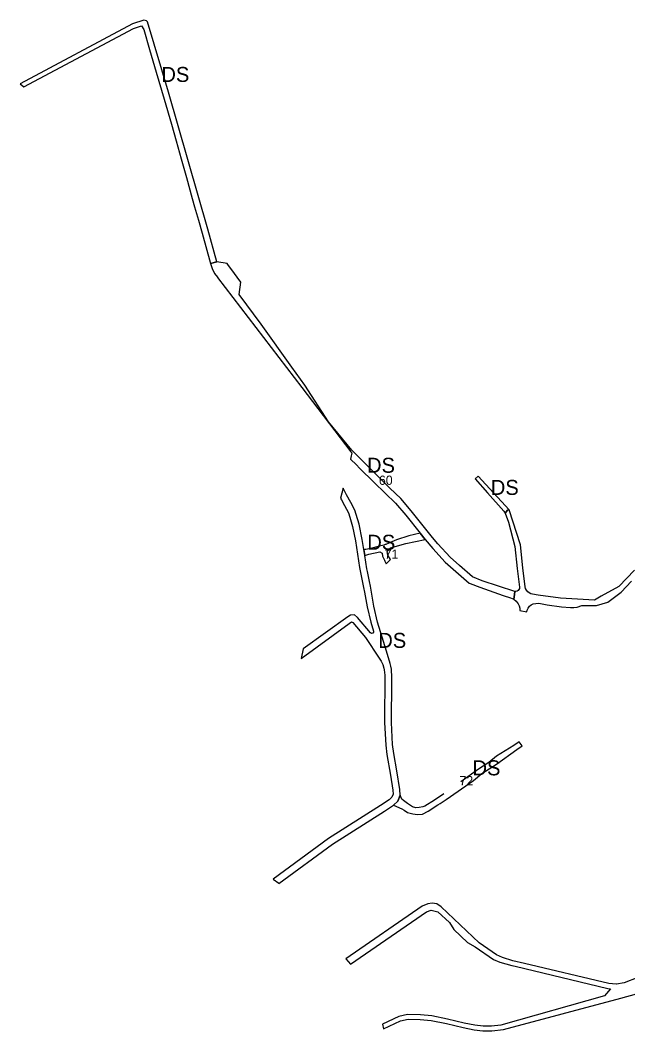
# Model space of a CAD drawing. Extents: x -535435 to -532834, y -1165802 to -1163866.
# Drawn here: x -535435 to -534910, y -1165594 to -1164720 of the extents above; entities that cross this region are included whole.
import ezdxf

# ---------------------------------------------------------------- set-up
doc = ezdxf.new("R2010")
doc.units = 0
for name, color, linetype in [('Level 4', 7, 'Continuous'), ('Level 43', 7, 'Continuous'), ('Level 5', 7, 'Continuous'), ('Level 61', 7, 'Continuous')]:
    doc.layers.add(name, color=color, linetype=linetype)

msp = doc.modelspace()

# ---------------------------------------------------------------- linework, layer by layer
at = {"layer": 'Level 4'}
for points in [[(-535330.07, -1164724.66), (-535328.05, -1164727.88), (-535322.98, -1164745.04), (-535317.16, -1164764.78), (-535310.26, -1164788.12), (-535304.15, -1164809.81), (-535300.1, -1164824.22), (-535295.73, -1164839.71), (-535291.17, -1164855.92), (-535286.04, -1164874.13), (-535284.01, -1164881.32), (-535280.81, -1164892.67), (-535277.63, -1164903.97), (-535270.21, -1164930.28), (-535264.94, -1164928.87), (-535272.55, -1164900.37), (-535306.74, -1164781.96), (-535324.72, -1164721.28), (-535325.54, -1164720.29), (-535327.93, -1164719.8), (-535337.8, -1164722.86), (-535434.81, -1164774.69), (-535431.57, -1164777.51), (-535336.95, -1164727.03)], [(-535015.48, -1165146.04), (-535013.47, -1165143.59), (-535012, -1165143.18), (-535038.78, -1165114.13), (-535041.39, -1165116.45), (-535030.79, -1165128.55), (-535016.81, -1165144.52)], [(-535148.99, -1165136.79), (-535152.58, -1165130.22), (-535155.67, -1165124.57), (-535157.81, -1165133.15), (-535157, -1165134.64), (-535154.36, -1165139.49), (-535151.12, -1165145.75), (-535149.97, -1165149.47), (-535147.45, -1165157.58), (-535144.99, -1165170.01), (-535141.61, -1165193.12), (-535139.69, -1165201.82), (-535137.97, -1165210.49), (-535137.13, -1165214.5), (-535134.97, -1165227.14), (-535131.59, -1165240.5), (-535129.33, -1165248.15), (-535129.39, -1165249.15), (-535130.06, -1165249.89), (-535131.05, -1165250.05), (-535131.92, -1165249.54), (-535143.16, -1165236.25), (-535145.86, -1165234.18), (-535149.38, -1165234.32), (-535151.45, -1165235.77), (-535190.12, -1165263.37), (-535192.03, -1165271.67), (-535150.48, -1165241.56), (-535148.51, -1165240.07), (-535147.29, -1165240.66), (-535136.4, -1165253.54), (-535124.44, -1165271.51), (-535122.72, -1165274.17), (-535121.35, -1165277.05), (-535120.36, -1165280.09), (-535120.06, -1165281.7), (-535119.6, -1165286.31), (-535119.85, -1165327.25), (-535118.83, -1165346.66), (-535117.83, -1165354.96), (-535114.74, -1165372.78), (-535112.59, -1165385.66), (-535112.44, -1165389.06), (-535113.51, -1165391.75), (-535115.81, -1165393.93), (-535123.19, -1165398.9), (-535168.13, -1165427.38), (-535216.21, -1165462.69), (-535211.33, -1165466.2), (-535211.12, -1165466.4), (-535164.75, -1165432.34), (-535119.96, -1165403.95), (-535112.03, -1165398.61), (-535108.43, -1165395.19), (-535106.38, -1165390.08), (-535106.61, -1165385.02), (-535109.32, -1165368.87), (-535111.89, -1165354.08), (-535112.85, -1165346.14), (-535113.85, -1165327.11), (-535113.63, -1165291.11), (-535113.6, -1165285.86), (-535113.67, -1165283.44), (-535113.92, -1165280.97), (-535114.34, -1165278.52), (-535114.92, -1165276.17), (-535118, -1165265.36), (-535125.87, -1165240.38), (-535128.96, -1165226.67), (-535132.1, -1165209.24), (-535132.91, -1165205.19), (-535134.64, -1165196.44), (-535135.08, -1165194.24), (-535136.92, -1165182.6), (-535137.7, -1165177.68), (-535139.07, -1165168.99), (-535141.76, -1165155.67), (-535144.39, -1165147.19), (-535145.54, -1165143.47)]]:
    msp.add_lwpolyline(points, close=True, dxfattribs=at)
msp.add_lwpolyline([(-534877.24, -1165538.36), (-534912.68, -1165552.42), (-534919.2, -1165553.5), (-534919.44, -1165553.53), (-534926.03, -1165552.84), (-534998.84, -1165535.55), (-535008.78, -1165533.19), (-535017.91, -1165530.5), (-535022.95, -1165527.99), (-535037.98, -1165517.6), (-535070.93, -1165486.65), (-535074.54, -1165483.89), (-535078.53, -1165483.39), (-535082.4, -1165484.03), (-535087.18, -1165485.86), (-535153.29, -1165531.56), (-535149.25, -1165536.15), (-535083.65, -1165491.01), (-535079.48, -1165489.46), (-535073.7, -1165490.85), (-535063.55, -1165500.03), (-535059.98, -1165506.16), (-535048.04, -1165517.37), (-535041.43, -1165521.13), (-535025.58, -1165532.21), (-535020.09, -1165534.38), (-535009.77, -1165537.3), (-535006.93, -1165537.98), (-534926.87, -1165557.06), (-534924.33, -1165557.42), (-534929.63, -1165563.61), (-535019.35, -1165588.86), (-535027.27, -1165589.76), (-535034.45, -1165589.68), (-535041.62, -1165588.86), (-535051.02, -1165587.04), (-535065.45, -1165583.66), (-535078.98, -1165580.85), (-535088.71, -1165579.86), (-535099.93, -1165579.7), (-535107.35, -1165581.35), (-535121.65, -1165588.06), (-535120.74, -1165592.05), (-535106.05, -1165585.16), (-535099.52, -1165583.71), (-535088.94, -1165583.86), (-535079.59, -1165584.81), (-535066.31, -1165587.57), (-535051.86, -1165590.95), (-535042.23, -1165592.82), (-535034.7, -1165593.68), (-535027.07, -1165593.76), (-535017, -1165592.62), (-534915.56, -1165565.61), (-534901.88, -1165561.94)], dxfattribs=at)
at = {"layer": 'Level 43'}
msp.add_line((-535007.21, -1165213.77), (-535007.59, -1165216.55), dxfattribs=at)
for points in [[(-534903.6, -1165195.4), (-534917.33, -1165209.45), (-534932.44, -1165217.99), (-534938.22, -1165221.25), (-534967.57, -1165219.55), (-534986.89, -1165216.91), (-534991.77, -1165216.24), (-534993.35, -1165215.85), (-534994.81, -1165215.12), (-534996.07, -1165214.09), (-534997.09, -1165212.82), (-534997.81, -1165211.36), (-534998.19, -1165209.78), (-535000.3, -1165193.52), (-535002.34, -1165173.49), (-535012, -1165143.18), (-535013.47, -1165143.59), (-535015.48, -1165146.04), (-535012.56, -1165153.94), (-535007.1, -1165174.89), (-535005.25, -1165194.06), (-535003.23, -1165210.2), (-535003.27, -1165211.17), (-535003.63, -1165212.15), (-535004.28, -1165212.98), (-535005.16, -1165213.55), (-535006.18, -1165213.83), (-535007.21, -1165213.77)], [(-535007.59, -1165216.55), (-535008.15, -1165220.62), (-535006, -1165222.24), (-535004.37, -1165224.4), (-535003.44, -1165226.23), (-535002.91, -1165228.22), (-535002.86, -1165230.27), (-534996.71, -1165231.47), (-534996.42, -1165230.01), (-534995.64, -1165228.23), (-534994.5, -1165226.67), (-534992.96, -1165225.5), (-534991.22, -1165224.64), (-534988.91, -1165224.17), (-534986.55, -1165224.07), (-534979.29, -1165225.46), (-534966.88, -1165227.19), (-534959.08, -1165227.75), (-534956.16, -1165227.72), (-534953.27, -1165227.27), (-534949.23, -1165225.98), (-534936.53, -1165225.98), (-534926.75, -1165223.13), (-534915.11, -1165214.3), (-534906.33, -1165204.96)]]:
    msp.add_lwpolyline(points, dxfattribs=at)
at = {"layer": 'Level 5'}
msp.add_lwpolyline([(-535168.38, -1165067.01), (-535188.74, -1165035.39), (-535199.87, -1165019.88), (-535226.52, -1164982.74), (-535245.62, -1164957.12), (-535244.09, -1164946.44), (-535252.72, -1164934.51), (-535254.68, -1164931.79), (-535255.81, -1164930.23), (-535264.94, -1164928.87), (-535270.21, -1164930.28), (-535268.78, -1164934.47), (-535266.73, -1164938.9), (-535264.29, -1164942.09), (-535264.1, -1164942.33), (-535191.37, -1165037.5), (-535149, -1165092.96), (-535148.04, -1165094.04), (-535148.98, -1165097.84), (-535149.34, -1165099.29), (-535143.98, -1165104.42), (-535141.33, -1165107.07), (-535128.93, -1165119.48), (-535119.4, -1165128.81), (-535110.22, -1165137.55), (-535101.4, -1165147.86), (-535089, -1165163.41), (-535084.68, -1165168.81), (-535078.15, -1165176.75), (-535067.39, -1165188.44), (-535046.59, -1165206.68), (-535045.87, -1165206.9), (-535037.55, -1165210.25), (-535017.13, -1165217.29), (-535010.94, -1165219.42), (-535008.15, -1165220.62), (-535007.59, -1165216.55), (-535007.21, -1165213.77), (-535035.41, -1165204.65), (-535043.9, -1165201.06), (-535055.09, -1165191.25), (-535063.19, -1165184.14), (-535073.74, -1165172.69), (-535078.39, -1165167.02), (-535096.77, -1165144.05), (-535105.85, -1165133.42), (-535115.23, -1165124.49), (-535148.12, -1165091.69)], close=True, dxfattribs=at)
for points in [[(-535089, -1165163.41), (-535098.68, -1165165.83), (-535109.53, -1165169.28), (-535113.55, -1165171.04), (-535118.73, -1165173.09), (-535119.16, -1165173.24), (-535120.44, -1165173.67), (-535124.14, -1165174.77), (-535131.91, -1165176.69), (-535136.05, -1165177.44), (-535137.7, -1165177.68), (-535136.92, -1165182.6), (-535133.44, -1165181.63), (-535123.79, -1165179.53), (-535121.98, -1165180.73), (-535121.5, -1165183.16), (-535119.98, -1165186.84), (-535119.49, -1165187.73), (-535118.3, -1165189.93), (-535114.67, -1165186.14), (-535117.08, -1165182.51), (-535117.51, -1165179.15), (-535114.59, -1165176.22), (-535101.55, -1165172.42), (-535084.68, -1165168.81), (-535089, -1165163.41)], [(-535068.42, -1165388.79), (-535076.52, -1165394.26), (-535084.9, -1165399.65), (-535086.71, -1165400.22), (-535089.82, -1165400.62), (-535092.83, -1165401.01), (-535095.7, -1165400.06), (-535099.89, -1165397.3), (-535103.39, -1165394.57), (-535104.97, -1165393.33), (-535106.38, -1165390.08), (-535108.43, -1165395.19), (-535112.03, -1165398.61), (-535105, -1165401.82), (-535102.85, -1165403.08), (-535099.85, -1165404.85), (-535095.44, -1165406), (-535091.32, -1165406.68), (-535087.09, -1165406.35), (-535082, -1165403.91), (-535073.65, -1165398.42), (-535071.8, -1165397.24), (-535066.46, -1165393.6), (-535043.05, -1165377.3), (-535035.57, -1165371.22), (-535023.05, -1165363.29), (-535005.4, -1165350.5), (-535000.94, -1165347.4), (-535003.45, -1165343.98), (-535008.17, -1165346.93), (-535023.08, -1165356.13), (-535029.62, -1165361.79), (-535038.58, -1165367.54), (-535053.88, -1165378.49)]]:
    msp.add_lwpolyline(points, dxfattribs=at)

# ---------------------------------------------------------------- texts
at = {"layer": 'Level 4'}
for p in [(-535312.75, -1164773.2), (-535027.94, -1165130.33), (-535125.23, -1165262.63)]:
    msp.add_text('DS', height=13, dxfattribs=at).set_placement(p)
at = {"layer": 'Level 5'}
for p in [(-535134.96, -1165111.19), (-535134.72, -1165177.81), (-535043.76, -1165372.86)]:
    msp.add_text('DS', height=13, dxfattribs=at).set_placement(p)
at = {"layer": 'Level 61'}
for s, p in [('60', (-535124.71, -1165121.63)), ('71', (-535119.79, -1165185.6)), ('72', (-535055.03, -1165381.52))]:
    msp.add_text(s, height=8, dxfattribs=at).set_placement(p)

doc.saveas('drawing.dxf')
